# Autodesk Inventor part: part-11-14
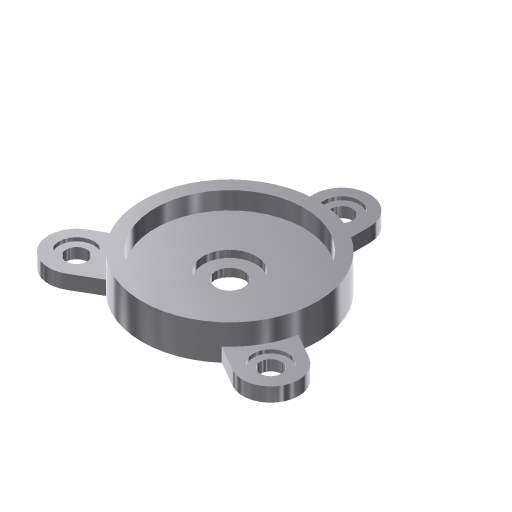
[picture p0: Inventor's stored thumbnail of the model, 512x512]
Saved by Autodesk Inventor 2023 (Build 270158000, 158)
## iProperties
Company: CADCIM Technologies
Part Number: part-11-14
Document SubType Name: Modeling
Created: 2002-12
Designer: deepak
Description: Sample Drawing
Engineer: Deepak
Vendor: CADSoft
Density: 1 g/cm^3
Material: Generic
Appearance: Metal-AL-6061 (Polished)
Control State: 0
Master: False
Checked Out: False
Shininess: 64.0
Length Units: 11269
Angle Units: 11279
Time Units: 11290
Mass Units: 11283
Length Display Precision: 3
Angle Display Precision: 2
Compacted: True
Density: 0.0
Volumn: 0.0
Area: 0.0
PropertySet Name: Model Information
Title: Aligned Section
Author: deepak
Revision Number: 4
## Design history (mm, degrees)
node "Sketch1"
sketch "Sketch2"
  geometry: L1 (0, 1)-(0, 5); L2 (0, 5)-(-21.25, 5); L3 (-21.25, 5)-(-21.25, 10); L4 (-21.25, 10)-(-25, 10); L5 (-25, 10)-(-25, 0); L6 (-25, 0)-(-5, 0); L7 (0, 1)-(-5, 1); L8 (-5, 1)-(-5, 0); 1 further point
  constraints: 16 end point, 3 parallel, 3 perpendicular, 1 horizontal, 1 horizontal alignment, 1 vertical, 1 vertical alignment, 1 other
  dimensions: "d0" = 50 diameter of L5 L1; "d1" = 10 diameter of L8 L1; "d2" = 42.5 diameter of L3 L1; "d3" = 10 distance of L4.end L5.end; "d4" = 1 distance of L7.end L6.end; "d5" = 4 distance of L1.start L1.end
revolve "Revolution1" sketch "Sketch2" stored, may be unused: angle "d6" = 90 deg
sketch "Sketch3"
  geometry: C1 r 21.25 at (0, 0) reference
hole "Hole1" sketch "Sketch3" at (0, 0) diameter "d7" = 8; stored, may be unused: countersink angle "d11" = 82 deg, drill point angle "d13" = 118 deg; dims "d8" = 6, "d9" = 15, "d10" = 2, "d12" = 8
sketch "Sketch4"
  geometry: L1 (8, 23.685)-(8, 32); L2 (-8, 32)-(-8, 23.685); C1 r 5 at (0, 0) reference; C2 r 25 at (0, 0) reference; A1 r 8 centre (0, 32) between (8, 32) and (-8, 32); A2 r 25 centre (0, 0) between (8, 23.685) and (-8, 23.685)
  constraints: 4 end point, 4 point on circle, 2 centre point, 2 concentric, 2 tangent, 2 vertical, 1 parallel
  dimensions: "d14" = 8 radius of A1; "d15" = 32 distance of C1.centre A1.centre
extrude "Extrusion1" join sketch "Sketch4" distance "d16" = 4; taper "d17" = 0 deg
sketch "Sketch5"
  geometry: A1 r 8 centre (0, 32) between (8, 32) and (-8, 32) reference
hole "Hole2" sketch "Sketch5" at (0, 32) diameter "d18" = 6; stored, may be unused: countersink angle "d22" = 82 deg, drill point angle "d24" = 118 deg; dims "d19" = 6, "d20" = 10, "d21" = 1, "d23" = 8
pattern_circular "Circular Pattern1" dims angle "d27" = 360 deg
body "Solid1"
